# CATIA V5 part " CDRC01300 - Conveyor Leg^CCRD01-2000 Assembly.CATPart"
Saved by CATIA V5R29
Part number:  CDRC01300 - Conveyor Leg^CCRD01-2000 Assembly
Definition: design
Source: Unknown
Bounding box of the stored display mesh (mm): x -290 to 290, y -314 to 304, z -62.5 to 62.5
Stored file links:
  C:\가치같이\SmartFactory_BoxErectorConveyor\ CDRC01300 - Conveyor Leg^CCRD01-2000 Assembly.CATPart
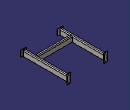
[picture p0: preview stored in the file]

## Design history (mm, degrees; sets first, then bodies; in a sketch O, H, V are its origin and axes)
Body1 "End cap1[4]" (main body)
  Solid1: solid without history
Body2 "End cap1[3]"
  Solid2: solid without history
Body3 "Rectangular tube 70 X 40 X 5(1)[3]"
  Solid3: solid without history
Body4 "Mirror1"
  Solid4: solid without history
Body5 "Break-Corner1"
  Solid5: solid without history
Body6 "End cap1[2]"
  Solid6: solid without history
Body7 "End cap1[1]"
  Solid7: solid without history
Body8 "Mirror2[2]"
  Solid8: solid without history
Body9 "Boss-Extrude1"
  Solid9: solid without history
Body10 "Mirror2[1]"
  Solid10: solid without history
Body11 "Break-Corner2"
  Solid11: solid without history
